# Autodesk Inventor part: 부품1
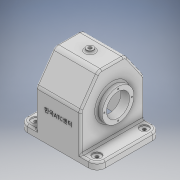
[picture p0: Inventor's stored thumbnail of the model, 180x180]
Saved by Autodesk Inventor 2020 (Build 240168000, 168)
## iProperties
Created: 2022-12
Part Number: 부품1
Material: 일반
Document SubType Name: Modeling
Designer: com
Density: 1 g/cm^3
Appearance: 기본값
Author: com
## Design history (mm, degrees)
sketch "스케치1"
  geometry: L1 (0, 0)-(-134, 0); L2 (-134, 0)-(-134, 110); L3 (-134, 110)-(0, 110); L4 (0, 110)-(0, 0)
  constraints: 8 end point, 2 parallel, 1 horizontal, 1 perpendicular
  dimensions: "d0" = 110 distance of L3.end L1.start; "d1" = 134 distance of L1.start L1.end
extrude "돌출1" new body sketch "스케치1" distance "d2" = 12; taper "d3" = 0 deg
fillet "모깎기1" dims "d4" = 14
sketch "스케치2"
  geometry: L1 (0, -14)-(0, -96) reference; L2 (14, -110)-(120, -110) reference; L3 (134, -96)-(134, -14) reference; L4 (120, 0)-(14, 0) reference; A1 r 14 centre (14, -14) between (14, 0) and (0, -14) reference; A2 r 14 centre (14, -96) between (0, -96) and (14, -110) reference; A3 r 14 centre (120, -96) between (120, -110) and (134, -96) reference; A4 r 14 centre (120, -14) between (134, -14) and (120, 0) reference; 5 further points
  constraints: 4 coincident
hole "구멍1" sketch "스케치2" at (14, -14), (14, -96), (120, -96), (120, -14) diameter "d5" = 5.5; stored, may be unused: countersink angle "d9" = 90 deg, drill point angle "d11" = 0 deg; dims "d6" = 30, "d7" = 15, "d8" = 2, "d10" = 37.3
node "작업 평면1"
sketch "스케치3"
  geometry: L1 (0, 12)-(-14, 12) reference; L2 (-14, 12)-(-14, 0) reference; L3 (-14, 0)-(0, 0) reference; L4 (0, 0)-(0, 12) reference; L5 (82, 12)-(96, 12) reference; L6 (96, 0)-(96, 12) reference; L7 (96, 0)-(82, 0) reference; L8 (-14, 12)-(-14, 0) reference; L9 (-14, 12)-(0, 12) reference; L10 (-14, 12)-(-14, 77); L11 (-14, 77)-(17.509, 122); L12 (17.509, 122)-(64.491, 122); L13 (64.491, 122)-(96, 77); L14 (96, 77)-(96, 12); L15 (0, 0)-(82, 0) reference
  constraints: 10 end point, 2 equal length, 2 perpendicular, 1 horizontal
  dimensions: "d12" = 65 distance of L1.end L10.end; "d13" = 35 deg angle of L10 L11; "d14" = 122 distance between parallel lines of L15 L12
extrude "돌출2" join sketch "스케치3" stored distance "d15" = 77; taper "d16" = 0 deg
node "작업 평면2"
sketch "스케치4"
  geometry: L1 (53, 151.2)-(53, -25.2) reference; L2 (53, 126)-(59, 126); L3 (14.5, 122)-(91.5, 122) reference; L4 (59, 126)-(59, 122); 2 further points
  constraints: 4 end point, 2 point on line, 1 horizontal, 1 perpendicular
  dimensions: "d17" = 4 distance of L2.end L4.end; "d18" = 6 distance of L2.start L2.end
revolve "회전1" sketch "스케치4" stored, may be unused: angle "d19" = 90 deg
sketch "스케치5"
  geometry: L1 (14, 12)-(-96, 12) reference; L2 (14, 12)-(14, 77) reference; L3 (14, 77)-(-17.509, 122) reference; L4 (-17.509, 122)-(-64.491, 122) reference; L5 (-64.491, 122)-(-96, 77) reference; L6 (-96, 77)-(-96, 12) reference; L7 (-47, 126)-(-35, 126) reference; C1 r 37.5 at (-41, 65); 1 further point
  constraints: 1 centre point
  dimensions: "d20" = 75 diameter of C1; "d21" = 61 distance from line of C1.centre L7
extrude "돌출3" join sketch "스케치5" distance "d22" = 5; taper "d23" = 0 deg
sketch "스케치6"
  geometry: L1 (96, 12)-(-14, 12) reference; L2 (96, 12)-(96, 77) reference; L3 (96, 77)-(64.491, 122) reference; L4 (64.491, 122)-(17.509, 122) reference; L5 (17.509, 122)-(-14, 77) reference; L6 (-14, 77)-(-14, 12) reference; L7 (35, 126)-(47, 126) reference; C1 r 27.469 at (41, 65); 1 further point
  constraints: 1 centre point
  dimensions: "d24" = 61 distance from line of C1.centre L7
extrude "돌출4" join sketch "스케치6" distance "d25" = 10; taper "d26" = 0 deg
sketch "스케치7"
  geometry: C1 r 37.5 at (0, 0) reference; C2 r 20 at (0, 0); 1 further point
  constraints: 1 centre point, 1 coincident
  dimensions: "d27" = 40 diameter of C2
extrude "돌출5" cut sketch "스케치7" extent not by distance; stored distance "d28" = 0; taper "d29" = 0 deg
sketch "스케치9"
  geometry: L1 (-14, 12)-(96, 12) reference; L2 (-14, 12)-(-14, 77) reference; L3 (-14, 77)-(17.509, 122) reference; L4 (17.509, 122)-(64.491, 122) reference; L5 (64.491, 122)-(96, 77) reference; L6 (96, 77)-(96, 12) reference; L7 (82, 0)-(0, 0) reference; L8 (82, 12)-(96, 12) reference; L9 (96, 12)-(96, 0) reference; L10 (96, 0)-(82, 0) reference; L11 (82, 0)-(82, 12) reference; L12 (61.888, 117)-(20.112, 117); L13 (20.112, 117)-(-9, 75.424); L14 (-9, 75.424)-(-9, 0); L15 (91, 0)-(91, 75.424); L16 (91, 75.424)-(61.888, 117); L17 (0, 0)-(-14, 0) reference; L18 (-14, 12)-(-14, 0) reference; L19 (91, 0)-(-9, 0); C1 r 37.5 at (41, 65) reference; 2 further points
  constraints: 12 end point, 2 point on line, 1 collinear, 3 other
  dimensions: "d41" = 5 distance between parallel lines of L3 L13
extrude "돌출7" cut sketch "스케치9" stored distance "d42" = 67; taper "d43" = 0 deg
fillet "모깎기2" dims "d44" = 3
fillet "모깎기3" dims "d45" = 10
fillet "모깎기4" dims "d46" = 10
fillet "모깎기5" dims "d47" = 10
fillet "모깎기6" dims "d48" = 3
fillet "모깎기7" dims "d49" = 3
sketch "스케치12"
  geometry: L1 (0, 27.469)-(0, 23.735); L2 (0, 23.735)-(0, 20); 8 further points
  constraints: 4 end point, 3 vertical alignment, 2 coincident, 2 vertical, 1 collinear, 9 other
  dimensions: "d64" = 360 deg dimension on point (0, 0) point (0, 23.735) (derived)
hole "구멍3" sketch "스케치12" at (0, 23.735), (-23.735, 0), (0, -23.735), (23.735, 0) diameter "d66" = 2.459; stored, may be unused: countersink angle "d70" = 82 deg, drill point angle "d72" = 118 deg; dims "d67" = 6, "d68" = 3, "d69" = 4.775, "d71" = 8
sketch "스케치13"
  geometry: L1 (0, 37.5)-(0, 28.75); L2 (0, 28.75)-(0, 20); 7 further points
  constraints: 4 end point, 3 vertical alignment, 2 vertical, 1 coincident, 1 collinear, 9 other
  dimensions: "d75" = 360 deg dimension on point (0, 0) point (0, 28.75) (derived)
hole "구멍4" sketch "스케치13" at (0, 28.75), (-28.75, 0), (0, -28.75), (28.75, 0) diameter "d77" = 2.459; stored, may be unused: countersink angle "d81" = 82 deg, drill point angle "d83" = 118 deg; dims "d78" = 6, "d79" = 3, "d80" = 4.775, "d82" = 8
sketch "스케치14"
  geometry: C1 r 6 at (0, 0) reference; 2 further points
  constraints: 1 coincident
hole "구멍5" sketch "스케치14" at (0, 0) diameter "d84" = 6; stored, may be unused: countersink angle "d88" = 82 deg, drill point angle "d90" = 118 deg; dims "d85" = 12, "d86" = 3, "d87" = 4.775, "d89" = 17.1
sketch "스케치15"
  geometry: L1 (0, 0)-(106, 0) reference; 2 further points
  constraints: 1 other
  dimensions: "d91" = 50 distance from line of L1 point (53, 50); "d92" = 67 horizontal distance of point (53, 50) point (-14, 0)
feature "엠보싱1" sketch "스케치15" dims "d0" = 110, "d1" = 134, "d93" = 1, "d94" = 0
fillet "모깎기8" dims "d95" = 3
node "솔리드1"
node "투영된 루프1"
node "투영된 루프2"
node "투영된 루프3"
node "투영된 루프4"
node "투영된 루프5"
node "투영된 루프6"
node "투영된 루프7"
node "투영된 루프9"
node "투영된 루프10"
node "투영된 루프11"
feature "A9D066F2-1C7D-4E18-AEED-F7BC21143FA4" dims "d5" = 5.5, "d6" = 30, "d7" = 15, "d8" = 2, "d9" = 90 deg, "d10" = 37.3, "d11" = 0
